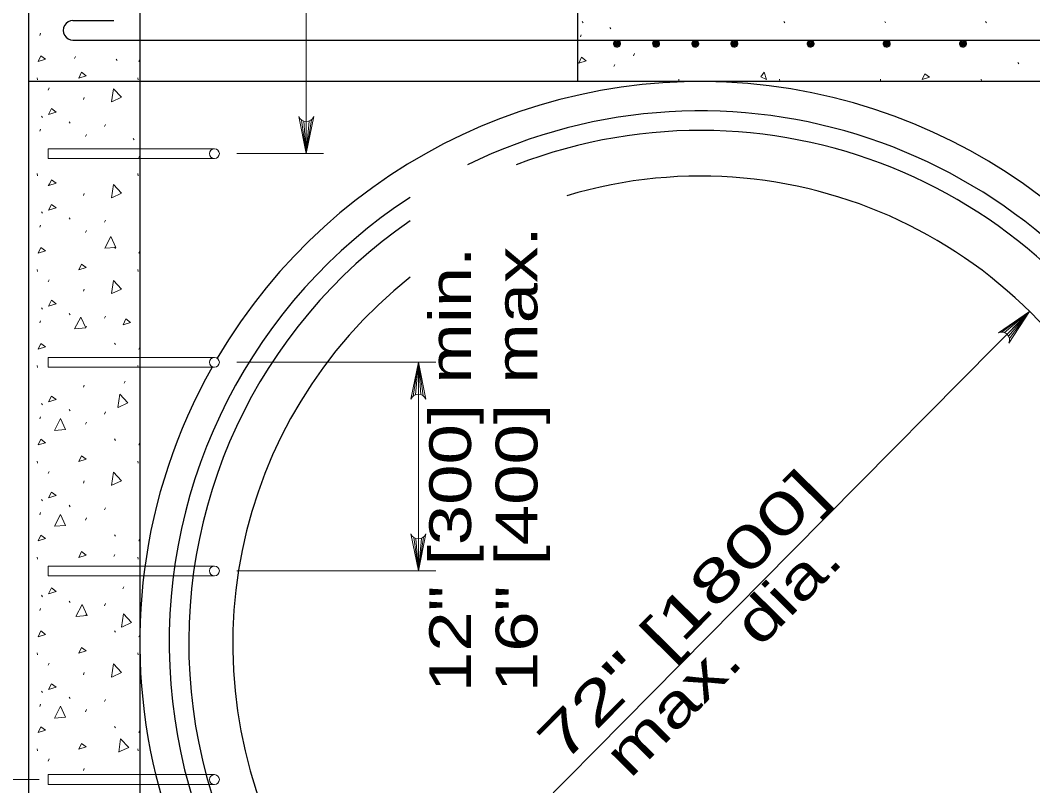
# Model space of a CAD drawing. Extents: x 1073.4 to 1107.4, y 719.4 to 741.4.
# Drawn here: x 1087.233 to 1091.113, y 725.295 to 728.228 of the extents above; entities that cross this region are included whole.
import ezdxf
from ezdxf.enums import TextEntityAlignment as Align

# ---------------------------------------------------------------- set-up
doc = ezdxf.new("R2010")
doc.units = 0
doc.header["$LTSCALE"] = 0.062
doc.linetypes.add('LONG_DASHED', pattern=[7.5, 6, -1.5])
doc.layers.add('1', color=7, linetype='Continuous', lineweight=13)

msp = doc.modelspace()

# ---------------------------------------------------------------- linework, layer by layer
at = {"layer": '1'}
for p, q in [((1088.32908, 727.71708), (1088.32908, 730.9745)), ((1089.38625, 728.22283), (1089.38983, 728.2175)), ((1090.15942, 728.22283), (1090.163, 728.2175)), ((1090.546, 728.22283), (1090.54958, 728.2175)), ((1090.93258, 728.22283), (1090.93617, 728.2175)), ((1087.30725, 728.16992), (1087.31075, 728.17792)), ((1089.3795, 728.16433), (1089.38308, 728.17233)), ((1089.49258, 728.20025), (1089.49617, 728.19492)), ((1087.44075, 728.08108), (1087.44433, 728.08908)), ((1089.58325, 728.09225), (1089.58683, 728.10025)), ((1087.60025, 728.07917), (1087.60375, 728.07383)), ((1087.68758, 728.06967), (1087.69092, 728.07658)), ((1087.69092, 728.07075), (1087.68758, 728.06967)), ((1089.50783, 728.0505), (1089.51133, 728.0585)), ((1091.0565, 728.06642), (1091.06, 728.06108)), ((1087.29758, 728.00758), (1087.29842, 727.99958)), ((1087.68408, 728.00758), (1087.685, 727.99958)), ((1089.37025, 727.999), (1089.37075, 727.99408)), ((1089.7565, 728.00208), (1089.75733, 727.99408)), ((1090.143, 728.00208), (1090.14392, 727.99408)), ((1090.52958, 728.00208), (1090.5305, 727.99408)), ((1090.91625, 728.00208), (1090.91717, 727.99408)), ((1087.33967, 727.96042), (1087.34325, 727.96842)), ((1087.47458, 727.92408), (1087.47817, 727.93208)), ((1088.32908, 727.71708), (1088.32908, 727.89542)), ((1087.31392, 727.86108), (1087.3175, 727.85575)), ((1087.42025, 727.8385), (1087.42383, 727.83317)), ((1087.55525, 727.82108), (1087.55892, 727.82908)), ((1088.31117, 727.84525), (1088.32908, 727.71708)), ((1088.32, 727.84092), (1088.32908, 727.71708)), ((1088.34892, 727.84675), (1088.32908, 727.71708)), ((1088.34058, 727.84183), (1088.32908, 727.71708)), ((1088.32908, 727.83958), (1088.32908, 727.71708)), ((1087.30725, 727.80267), (1087.31075, 727.81058)), ((1087.48342, 727.78225), (1087.487, 727.79017)), ((1087.66575, 727.77508), (1087.66925, 727.76975)), ((1087.68758, 727.70233), (1087.69092, 727.70925)), ((1087.69092, 727.70342), (1087.68758, 727.70233)), ((1087.97708, 727.73583), (1087.69092, 727.73583)), ((1088.39567, 727.71708), (1088.06258, 727.71708)), ((1087.97708, 727.69825), (1087.69092, 727.69825)), ((1087.29758, 727.64025), (1087.29842, 727.63225)), ((1087.68408, 727.64025), (1087.685, 727.63225)), ((1087.33967, 727.59308), (1087.34325, 727.60108)), ((1087.47458, 727.55675), (1087.47817, 727.56475)), ((1087.31392, 727.49375), (1087.3175, 727.48842)), ((1087.42025, 727.47117), (1087.42383, 727.46583)), ((1087.30725, 727.43533), (1087.31075, 727.44333)), ((1087.55525, 727.45383), (1087.55892, 727.46183)), ((1087.48342, 727.41492), (1087.487, 727.42283)), ((1087.59442, 727.35808), (1087.59792, 727.35275)), ((1087.68758, 727.33508), (1087.69092, 727.342)), ((1087.69092, 727.33608), (1087.68758, 727.33508)), ((1087.29758, 727.27292), (1087.29842, 727.26492)), ((1087.68408, 727.27292), (1087.685, 727.26492)), ((1087.33967, 727.22583), (1087.34325, 727.23375)), ((1087.47458, 727.18942), (1087.47817, 727.19742)), ((1087.31392, 727.12642), (1087.3175, 727.12108)), ((1087.42025, 727.10392), (1087.42383, 727.09858)), ((1087.55525, 727.0865), (1087.55892, 727.0945)), ((1090.99608, 727.03342), (1091.10083, 727.11242)), ((1091.0055, 727.03108), (1091.10083, 727.11242)), ((1091.01533, 727.02467), (1091.10083, 727.11242)), ((1091.02092, 727.01742), (1091.10083, 727.11242)), ((1091.02425, 727.00808), (1091.10083, 727.11242)), ((1087.30725, 727.068), (1087.31075, 727.076)), ((1087.48342, 727.04758), (1087.487, 727.05558)), ((1087.59442, 726.99075), (1087.59792, 726.98542)), ((1087.68758, 726.96775), (1087.69092, 726.97467)), ((1087.69092, 726.96875), (1087.68758, 726.96775)), ((1087.97708, 726.93633), (1087.69092, 726.93633)), ((1087.29758, 726.90558), (1087.29842, 726.89767)), ((1087.68408, 726.90558), (1087.685, 726.89767)), ((1087.97708, 726.89875), (1087.69092, 726.89875)), ((1088.06258, 726.9175), (1088.82525, 726.9175)), ((1088.73883, 726.78783), (1088.75858, 726.9175)), ((1088.74708, 726.79275), (1088.75858, 726.9175)), ((1088.75858, 726.118), (1088.75858, 726.9175)), ((1088.75858, 726.795), (1088.75858, 726.9175)), ((1088.76767, 726.79367), (1088.75858, 726.9175)), ((1088.77658, 726.78933), (1088.75858, 726.9175)), ((1087.47458, 726.82208), (1087.47817, 726.83008)), ((1087.631, 726.83758), (1087.63458, 726.84558)), ((1087.31392, 726.75917), (1087.3175, 726.75383)), ((1087.42025, 726.73658), (1087.42383, 726.73125)), ((1087.30725, 726.70067), (1087.31075, 726.70867)), ((1087.55525, 726.71917), (1087.55892, 726.72717)), ((1087.48342, 726.68025), (1087.487, 726.68825)), ((1087.59442, 726.62342), (1087.59792, 726.61808)), ((1087.68758, 726.60042), (1087.69092, 726.60733)), ((1087.69092, 726.60142), (1087.68758, 726.60042)), ((1087.29758, 726.53825), (1087.29842, 726.53042)), ((1087.68408, 726.53825), (1087.685, 726.53042)), ((1087.33967, 726.49117), (1087.34325, 726.49917)), ((1087.47458, 726.45475), (1087.47817, 726.46275)), ((1087.31392, 726.39183), (1087.3175, 726.3865)), ((1087.42025, 726.36925), (1087.42383, 726.36392)), ((1087.55525, 726.35183), (1087.55892, 726.35983)), ((1087.30725, 726.33333), (1087.31075, 726.34133)), ((1087.48342, 726.31292), (1087.487, 726.32092)), ((1087.59442, 726.25608), (1087.59792, 726.25075)), ((1087.68758, 726.23308), (1087.69092, 726.24)), ((1087.69092, 726.23408), (1087.68758, 726.23308)), ((1088.74067, 726.24617), (1088.75858, 726.118)), ((1088.74958, 726.24183), (1088.75858, 726.118)), ((1088.77842, 726.24775), (1088.75858, 726.118)), ((1088.77017, 726.24275), (1088.75858, 726.118)), ((1088.75858, 726.2405), (1088.75858, 726.118)), ((1087.29758, 726.171), (1087.29842, 726.16308)), ((1087.59167, 726.17317), (1087.59525, 726.18117)), ((1087.68408, 726.171), (1087.685, 726.16308)), ((1087.69092, 726.12892), (1087.68992, 726.12875)), ((1087.69092, 726.12883), (1087.68992, 726.12867)), ((1087.69092, 726.12875), (1087.68992, 726.12858)), ((1087.97708, 726.13675), (1087.69092, 726.13675)), ((1088.06258, 726.118), (1088.82525, 726.118)), ((1087.97708, 726.09917), (1087.69092, 726.09917)), ((1087.62592, 726.04917), (1087.6295, 726.05717)), ((1087.31392, 726.0245), (1087.3175, 726.01917)), ((1087.42025, 726.00192), (1087.42383, 725.99658)), ((1087.55525, 725.9845), (1087.55892, 725.9925)), ((1087.30725, 725.966), (1087.31075, 725.974)), ((1087.48342, 725.94567), (1087.487, 725.95367)), ((1087.59442, 725.88875), (1087.59792, 725.88342)), ((1087.68758, 725.86575), (1087.69092, 725.87267)), ((1087.69092, 725.86675), (1087.68758, 725.86575)), ((1087.29758, 725.80367), (1087.29842, 725.79575)), ((1087.68408, 725.80367), (1087.685, 725.79575)), ((1087.33967, 725.75658), (1087.34325, 725.76458)), ((1087.47458, 725.72017), (1087.47817, 725.72808)), ((1087.31392, 725.65717), (1087.3175, 725.65183)), ((1087.30725, 725.59875), (1087.31075, 725.60675)), ((1087.42025, 725.63458), (1087.42383, 725.62925)), ((1087.55525, 725.61717), (1087.55892, 725.62517)), ((1087.48342, 725.57833), (1087.487, 725.58633)), ((1087.59442, 725.52142), (1087.59792, 725.51608)), ((1087.68758, 725.49842), (1087.69092, 725.50533)), ((1087.69092, 725.49942), (1087.68758, 725.49842)), ((1087.29758, 725.43642), (1087.29842, 725.42842)), ((1087.68408, 725.43642), (1087.685, 725.42842)), ((1087.33967, 725.38925), (1087.34325, 725.39725)), ((1087.47458, 725.35283), (1087.47817, 725.36083)), ((1087.97708, 725.33725), (1087.69092, 725.33725)), ((1086.64542, 725.31842), (1087.30583, 725.31842)), ((1087.69092, 725.32942), (1087.68992, 725.32917)), ((1087.69092, 725.32933), (1087.68992, 725.32908)), ((1087.69092, 725.32925), (1087.68992, 725.32908)), ((1087.69092, 725.32917), (1087.68992, 725.329)), ((1087.97708, 725.29967), (1087.69092, 725.29967))]:
    msp.add_line(p, q, dxfattribs=at)
at = {"layer": '1', "lineweight": 25}
for p, q in [((1089.37025, 727.99275), (1089.36958, 728.84642)), ((1087.69092, 728.44875), (1087.69092, 724.04508)), ((1087.43475, 728.22683), (1087.59108, 728.22683)), ((1087.43475, 728.15183), (1088.59667, 728.15183)), ((1088.59667, 728.15183), (1091.94608, 728.15183)), ((1088.59667, 727.99275), (1087.26608, 727.99275)), ((1092.41392, 727.99275), (1088.59667, 727.99275))]:
    msp.add_line(p, q, dxfattribs=at)
at = {"layer": '1', "linetype": 'LONG_DASHED'}
for p, q in [((1087.33917, 727.73583), (1087.33917, 727.69825)), ((1087.69092, 727.73583), (1087.33917, 727.73583)), ((1087.69092, 727.69825), (1087.33917, 727.69825)), ((1087.33917, 726.93633), (1087.33917, 726.89875)), ((1087.69092, 726.93633), (1087.33917, 726.93633)), ((1087.69092, 726.89875), (1087.33917, 726.89875)), ((1087.33917, 726.13675), (1087.33917, 726.09917)), ((1087.69092, 726.13675), (1087.33917, 726.13675)), ((1087.69092, 726.09917), (1087.33917, 726.09917)), ((1087.33917, 725.33725), (1087.33917, 725.29967)), ((1087.69092, 725.33725), (1087.33917, 725.33725)), ((1087.69092, 725.29967), (1087.33917, 725.29967))]:
    msp.add_line(p, q, dxfattribs=at)
at = {"layer": '1', "lineweight": 25}
msp.add_lwpolyline([(1092.41392, 723.54533), (1087.26608, 723.54533), (1087.26608, 728.54242)], dxfattribs=at)
at = {"layer": '1'}
for points in [[(1087.301, 728.06967), (1087.31158, 728.09183), (1087.32942, 728.0785)], [(1089.37333, 728.06408), (1089.38392, 728.08625), (1089.40167, 728.07292)], [(1087.457, 728.00625), (1087.46758, 728.02842), (1087.48542, 728.01508)], [(1090.09342, 728.001), (1090.07125, 728.01167), (1090.08458, 728.02942)], [(1090.68908, 728.00067), (1090.69967, 728.02283), (1090.7175, 728.0095)], [(1087.34142, 727.86733), (1087.35208, 727.8895), (1087.36992, 727.87617)], [(1087.34225, 727.59442), (1087.35283, 727.61667), (1087.37058, 727.60333)], [(1087.34142, 727.5), (1087.35208, 727.52217), (1087.36992, 727.50883)], [(1087.301, 727.33508), (1087.31158, 727.35717), (1087.32942, 727.34392)], [(1087.457, 727.27158), (1087.46758, 727.29375), (1087.48542, 727.28042)], [(1087.34142, 727.13267), (1087.35208, 727.15483), (1087.36992, 727.1415)], [(1087.6275, 727.06108), (1087.63808, 727.08325), (1087.65592, 727.06992)], [(1087.301, 726.96775), (1087.31158, 726.98992), (1087.32942, 726.97658)], [(1087.34142, 726.76542), (1087.35208, 726.7875), (1087.36992, 726.77417)], [(1087.301, 726.60042), (1087.31158, 726.62258), (1087.32942, 726.60925)], [(1087.457, 726.53692), (1087.46758, 726.55908), (1087.48542, 726.54575)], [(1087.34142, 726.39808), (1087.35208, 726.42025), (1087.36992, 726.40692)], [(1087.301, 726.23308), (1087.31158, 726.25525), (1087.32942, 726.24192)], [(1087.457, 726.16967), (1087.46758, 726.19175), (1087.48542, 726.1785)], [(1087.34142, 726.03075), (1087.35208, 726.05292), (1087.36992, 726.03958)], [(1087.301, 725.86575), (1087.31158, 725.88792), (1087.32942, 725.87458)], [(1087.457, 725.80233), (1087.46758, 725.8245), (1087.48542, 725.81117)], [(1087.34142, 725.66342), (1087.35208, 725.68558), (1087.36992, 725.67225)], [(1087.301, 725.49842), (1087.31158, 725.52058), (1087.32942, 725.50725)], [(1087.457, 725.435), (1087.46758, 725.45717), (1087.48542, 725.44383)]]:
    msp.add_lwpolyline(points, close=True, dxfattribs=at)
for points in [[(1087.58258, 727.91492), (1087.58958, 727.96567), (1087.62133, 727.93275), (1087.58333, 727.91525)], [(1088.35742, 727.85867), (1088.32908, 727.71708), (1088.30075, 727.85867)], [(1087.58258, 727.54758), (1087.58958, 727.59833), (1087.62133, 727.5655), (1087.58333, 727.54792)], [(1087.55658, 727.35433), (1087.58058, 727.39958), (1087.59925, 727.35783), (1087.55758, 727.35433)], [(1087.58258, 727.18033), (1087.58958, 727.23108), (1087.62133, 727.19817), (1087.58333, 727.18058)], [(1087.44092, 727.04533), (1087.46492, 727.09058), (1087.48358, 727.04883), (1087.44192, 727.04533)], [(1088.57933, 724.56308), (1090.19025, 726.19175), (1091.10083, 727.11242)], [(1090.98175, 727.03075), (1091.10083, 727.11242), (1091.02225, 726.99125)], [(1088.73025, 726.77592), (1088.75858, 726.9175), (1088.78692, 726.77592)], [(1087.60692, 726.74425), (1087.61392, 726.79492), (1087.64567, 726.76208), (1087.60767, 726.7445)], [(1087.36358, 726.65625), (1087.38758, 726.7015), (1087.40625, 726.65975), (1087.36458, 726.65625)], [(1087.58258, 726.44567), (1087.58958, 726.49642), (1087.62133, 726.4635), (1087.58333, 726.44592)], [(1087.36358, 726.289), (1087.38758, 726.33417), (1087.40625, 726.2925), (1087.36458, 726.289)], [(1088.78692, 726.25958), (1088.75858, 726.118), (1088.73025, 726.25958)], [(1087.44625, 725.94342), (1087.47025, 725.98867), (1087.48892, 725.947), (1087.44717, 725.94342)], [(1087.62083, 725.90242), (1087.62792, 725.95317), (1087.65958, 725.92033), (1087.62158, 725.90275)], [(1087.58258, 725.71108), (1087.58958, 725.76175), (1087.62133, 725.72883), (1087.58333, 725.71133)], [(1087.36358, 725.55433), (1087.38758, 725.59967), (1087.40625, 725.55792), (1087.36458, 725.55433)], [(1087.61033, 725.42383), (1087.61742, 725.47458), (1087.64917, 725.44175), (1087.61117, 725.42408)]]:
    msp.add_lwpolyline(points, dxfattribs=at)
for centre, start, end in [((1088.32904, 727.87011), 202.08782, 337.91395), ((1090.99405, 727.0028), 337.82443, 113.65056), ((1088.75864, 726.76449), 22.08782, 157.91395), ((1088.75858, 726.27103), 202.08782, 337.91395)]:
    msp.add_arc(centre, 0.03056, start, end, dxfattribs=at)
at = {"layer": '1', "lineweight": 25}
for centre, major_axis, start_param, end_param in [((1087.43476, 728.18933), (0.03752, 0), 1.5707963, 4.712389), ((1089.84007, 725.84401), (2.03654, 0), 5.2000511, 8.308237), ((1089.8401, 725.84401), (2.14899, 0), 5.291026, 8.8932394), ((1089.8401, 725.84398), (1.96158, 0), 5.1222386, 8.2222672), ((1089.8401, 725.83775), (1.79289, 0), 5.1381757, 8.1439338), ((1089.84007, 725.84401), (2.03654, 0), 2.1491781, 4.2247268), ((1089.8401, 725.84398), (1.96158, 0), 2.1743579, 4.3025393), ((1089.8401, 725.83775), (1.79289, 0), 2.2407888, 5.0382117), ((1089.8401, 725.84401), (2.14899, 0), 2.6285244, 4.1337519)]:
    msp.add_ellipse(centre, major_axis=major_axis, ratio=0.999895, start_param=start_param, end_param=end_param, dxfattribs=at)
at = {"layer": '1'}
for centre, major_axis, start_param, end_param in [((1089.51998, 728.13816), (0.01369, 0), 1.8915099, 7.9683372), ((1089.51998, 728.13816), (0.01192, 0), 1.8915085, 7.9683359), ((1089.51998, 728.13816), (0.00893, 0), 1.891505, 7.9683328), ((1089.51998, 728.13816), (0.00724, 0), 1.8915017, 7.9683299), ((1089.51998, 728.13816), (0.00477, 0), 1.8914926, 7.968322), ((1089.51998, 728.13816), (0.00188, 0), 1.8914519, 7.9682863), ((1089.66991, 728.13816), (0.01369, 0), 1.8915099, 7.9683372), ((1089.66991, 728.13816), (0.01192, 0), 1.8915085, 7.9683359), ((1089.66991, 728.13816), (0.00893, 0), 1.891505, 7.9683328), ((1089.66991, 728.13816), (0.00724, 0), 1.8915017, 7.9683299), ((1089.66991, 728.13816), (0.00477, 0), 1.8914926, 7.968322), ((1089.66991, 728.13816), (0.00188, 0), 1.8914519, 7.9682863), ((1089.81984, 728.13816), (0.01369, 0), 1.8915099, 7.9683372), ((1089.81984, 728.13816), (0.01192, 0), 1.8915085, 7.9683359), ((1089.81984, 728.13816), (0.00893, 0), 1.891505, 7.9683328), ((1089.81984, 728.13816), (0.00724, 0), 1.8915017, 7.9683299), ((1089.81984, 728.13816), (0.00477, 0), 1.8914926, 7.968322), ((1089.81984, 728.13816), (0.00188, 0), 1.8914519, 7.9682863), ((1089.96977, 728.13816), (0.01369, 0), 1.8915099, 7.9683372), ((1089.96977, 728.13816), (0.01192, 0), 1.8915085, 7.9683359), ((1089.96977, 728.13816), (0.00893, 0), 1.891505, 7.9683328), ((1089.96977, 728.13816), (0.00724, 0), 1.8915017, 7.9683299), ((1089.96977, 728.13816), (0.00477, 0), 1.8914926, 7.968322), ((1089.96977, 728.13816), (0.00188, 0), 1.8914519, 7.9682863), ((1090.26183, 728.13816), (0.01369, 0), 1.8915099, 7.9683372), ((1090.26183, 728.13816), (0.01192, 0), 1.8915085, 7.9683359), ((1090.26183, 728.13816), (0.00893, 0), 1.891505, 7.9683328), ((1090.26183, 728.13816), (0.00724, 0), 1.8915017, 7.9683299), ((1090.26183, 728.13816), (0.00477, 0), 1.8914926, 7.968322), ((1090.26183, 728.13816), (0.00188, 0), 1.8914519, 7.9682863), ((1090.5539, 728.13816), (0.01369, 0), 1.8915099, 7.9683372), ((1090.5539, 728.13816), (0.01192, 0), 1.8915085, 7.9683359), ((1090.5539, 728.13816), (0.00893, 0), 1.891505, 7.9683328), ((1090.5539, 728.13816), (0.00724, 0), 1.8915017, 7.9683299), ((1090.5539, 728.13816), (0.00477, 0), 1.8914926, 7.968322), ((1090.5539, 728.13816), (0.00188, 0), 1.8914519, 7.9682863), ((1090.84596, 728.13816), (0.01369, 0), 1.8915099, 7.9683372), ((1090.84596, 728.13816), (0.01192, 0), 1.8915085, 7.9683359), ((1090.84596, 728.13816), (0.00893, 0), 1.891505, 7.9683328), ((1090.84596, 728.13816), (0.00724, 0), 1.8915017, 7.9683299), ((1090.84596, 728.13816), (0.00477, 0), 1.8914926, 7.968322), ((1090.84596, 728.13816), (0.00188, 0), 1.8914519, 7.9682863)]:
    msp.add_ellipse(centre, major_axis=major_axis, ratio=0.999895, start_param=start_param, end_param=end_param, dxfattribs=at)
for centre in [(1087.97714, 727.71707), (1087.97714, 726.91753), (1087.97714, 726.11799), (1087.97714, 725.31845)]:
    msp.add_ellipse(centre, major_axis=(0.01876, 0), ratio=0.999895, dxfattribs=at)

# ---------------------------------------------------------------- texts
at = {"layer": '1', "width": 1.3}
for s, p in [('16" [400] max.', (1089.21492, 725.65375)), ('12" [300] min.', (1088.9605, 725.65375))]:
    msp.add_text(s, height=0.16, rotation=90, dxfattribs=at).set_placement(p)
at = {"layer": '1'}
for s, width, p in [('72" [1800]', 1.5, (1089.82349, 725.89199)), ('max. dia.', 1.35, (1089.98201, 725.73524))]:
    msp.add_text(s, height=0.16, rotation=45.314, dxfattribs=dict(at, width=width)).set_placement(p, align=Align.CENTER)

doc.saveas('drawing.dxf')
